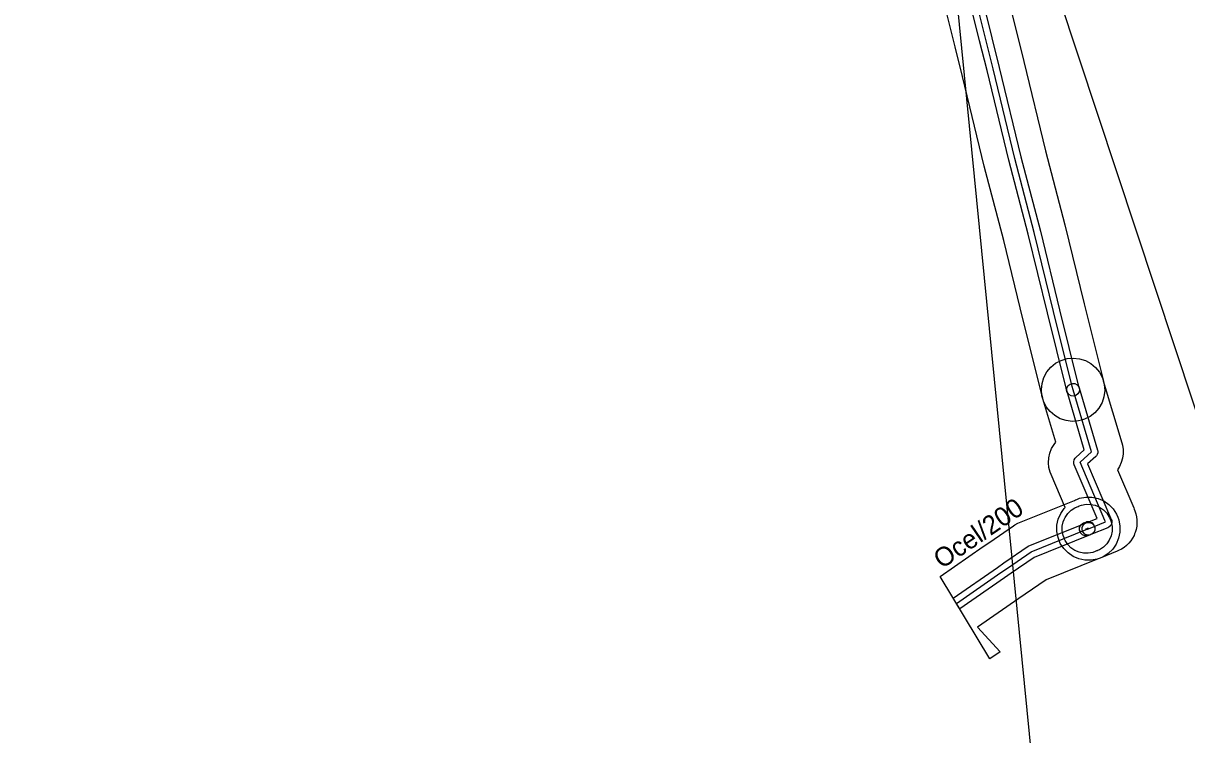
# Model space of a CAD drawing. Extents: x -555222 to -543220, y -1067119 to -1030889.
# Drawn here: x -550559 to -549821, y -1047415 to -1046964 of the extents above; entities that cross this region are included whole.
import ezdxf

# ---------------------------------------------------------------- set-up
doc = ezdxf.new("R2010")
doc.units = 0
for name, color, linetype in [('07_OCH_P A POPISY TI', 7, 'Continuous'), ('07_PLYNOVOD', 7, 'Continuous'), ('07_SDĚLOVACÍ', 7, 'Continuous')]:
    doc.layers.add(name, color=color, linetype=linetype)

msp = doc.modelspace()

# ---------------------------------------------------------------- linework, layer by layer
at = {"layer": '07_OCH_P A POPISY TI'}
for p, q in [((-549936.9, -1046937.01), (-549928.95, -1046969.41)), ((-549967.77, -1046979.03), (-549975.68, -1046946.81)), ((-549952.24, -1046975.18), (-549960.17, -1046942.89)), ((-549952.41, -1046940.93), (-549944.48, -1046973.26)), ((-549947.55, -1046993.93), (-549952.24, -1046975.18)), ((-549944.48, -1046973.26), (-549939.79, -1046992.01)), ((-549928.95, -1046969.41), (-549924.25, -1046988.19)), ((-549963.09, -1046997.75), (-549967.77, -1046979.03)), ((-549924.25, -1046988.19), (-549910.54, -1047044.87)), ((-549949.32, -1047054.65), (-549963.09, -1046997.75)), ((-549933.81, -1047050.74), (-549947.55, -1046993.93)), ((-549939.79, -1046992.01), (-549926.05, -1047048.78)), ((-549926.05, -1047048.78), (-549913.71, -1047095.83)), ((-549910.54, -1047044.87), (-549898.2, -1047091.9)), ((-549936.98, -1047101.72), (-549949.32, -1047054.65)), ((-549921.47, -1047097.79), (-549933.81, -1047050.74)), ((-549898.2, -1047091.9), (-549885.95, -1047141.98)), ((-549924.79, -1047151.56), (-549936.98, -1047101.72)), ((-549909.25, -1047147.73), (-549921.47, -1047097.79)), ((-549913.71, -1047095.83), (-549901.49, -1047145.81)), ((-549901.49, -1047145.81), (-549889.64, -1047193.48)), ((-549885.95, -1047141.98), (-549874.16, -1047189.41)), ((-549912.86, -1047199.57), (-549924.79, -1047151.56)), ((-549897.38, -1047195.5), (-549909.25, -1047147.73)), ((-549909.6, -1047185.21), (-549907.08, -1047182.18)), ((-549907.08, -1047182.18), (-549904.02, -1047179.7)), ((-549904.02, -1047179.7), (-549900.53, -1047177.86)), ((-549900.53, -1047177.86), (-549898.64, -1047177.3)), ((-549898.64, -1047177.3), (-549896.75, -1047176.74)), ((-549896.75, -1047176.74), (-549892.83, -1047176.38)), ((-549892.83, -1047176.38), (-549888.91, -1047176.8)), ((-549888.91, -1047176.8), (-549885.15, -1047177.96)), ((-549885.15, -1047177.96), (-549881.69, -1047179.84)), ((-549881.69, -1047179.84), (-549878.66, -1047182.36)), ((-549878.66, -1047182.36), (-549876.18, -1047185.42)), ((-549912.64, -1047192.43), (-549911.48, -1047188.67)), ((-549911.48, -1047188.67), (-549909.6, -1047185.21)), ((-549876.18, -1047185.42), (-549874.34, -1047188.91)), ((-549874.34, -1047188.91), (-549873.78, -1047190.8)), ((-549874.16, -1047189.41), (-549873.68, -1047191.15)), ((-549913.06, -1047196.35), (-549912.64, -1047192.43)), ((-549912.7, -1047200.27), (-549913.06, -1047196.35)), ((-549896.82, -1047197.55), (-549897.38, -1047195.5)), ((-549897.02, -1047196.85), (-549896.86, -1047195.27)), ((-549896.8, -1047197.62), (-549897.02, -1047196.85)), ((-549896.86, -1047195.27), (-549896.1, -1047193.87)), ((-549896.6, -1047198.31), (-549896.82, -1047197.55)), ((-549885.83, -1047234.62), (-549896.8, -1047197.62)), ((-549896.1, -1047193.87), (-549894.86, -1047192.87)), ((-549894.86, -1047192.87), (-549894.1, -1047192.64)), ((-549894.1, -1047192.64), (-549893.33, -1047192.42)), ((-549893.33, -1047192.42), (-549891.75, -1047192.58)), ((-549891.75, -1047192.58), (-549890.35, -1047193.34)), ((-549890.35, -1047193.34), (-549889.35, -1047194.58)), ((-549889.09, -1047197.76), (-549889.87, -1047199.14)), ((-549889.64, -1047193.48), (-549889.1, -1047195.41)), ((-549889.35, -1047194.58), (-549889.12, -1047195.34)), ((-549889.12, -1047195.34), (-549877.44, -1047234.75)), ((-549889.1, -1047195.41), (-549888.89, -1047196.18)), ((-549888.89, -1047196.18), (-549889.09, -1047197.76)), ((-549873.78, -1047190.8), (-549862.1, -1047230.21)), ((-549873.68, -1047191.15), (-549873.16, -1047193.05)), ((-549872.87, -1047196.98), (-549873.35, -1047200.89)), ((-549873.16, -1047193.05), (-549872.87, -1047196.98)), ((-549912.24, -1047201.81), (-549912.86, -1047199.57)), ((-549912.14, -1047202.16), (-549912.7, -1047200.27)), ((-549911.71, -1047203.71), (-549912.24, -1047201.81)), ((-549903.96, -1047229.76), (-549912.14, -1047202.16)), ((-549909.94, -1047207.23), (-549911.71, -1047203.71)), ((-549895.62, -1047199.57), (-549896.6, -1047198.31)), ((-549894.24, -1047200.35), (-549895.62, -1047199.57)), ((-549892.66, -1047200.55), (-549894.24, -1047200.35)), ((-549891.89, -1047200.34), (-549892.66, -1047200.55)), ((-549891.13, -1047200.12), (-549891.89, -1047200.34)), ((-549889.87, -1047199.14), (-549891.13, -1047200.12)), ((-549874.59, -1047204.63), (-549876.53, -1047208.06)), ((-549873.35, -1047200.89), (-549874.59, -1047204.63)), ((-549907.52, -1047210.33), (-549909.94, -1047207.23)), ((-549904.54, -1047212.91), (-549907.52, -1047210.33)), ((-549879.11, -1047211.04), (-549882.21, -1047213.46)), ((-549876.53, -1047208.06), (-549879.11, -1047211.04)), ((-549901.11, -1047214.85), (-549904.54, -1047212.91)), ((-549897.37, -1047216.09), (-549901.11, -1047214.85)), ((-549893.46, -1047216.57), (-549897.37, -1047216.09)), ((-549889.53, -1047216.28), (-549893.46, -1047216.57)), ((-549887.63, -1047215.76), (-549889.53, -1047216.28)), ((-549885.73, -1047215.23), (-549887.63, -1047215.76)), ((-549882.21, -1047213.46), (-549885.73, -1047215.23)), ((-549907.73, -1047236.69), (-549906.61, -1047233.81)), ((-549906.61, -1047233.81), (-549905.06, -1047231.14)), ((-549905.06, -1047231.14), (-549903.96, -1047229.76)), ((-549891.21, -1047239.52), (-549885.83, -1047234.62)), ((-549877.44, -1047234.75), (-549877.28, -1047235.29)), ((-549862.1, -1047230.21), (-549861.7, -1047231.55)), ((-549861.7, -1047231.55), (-549861.29, -1047234.33)), ((-549861.29, -1047234.33), (-549861.27, -1047237.13)), ((-549908.58, -1047242.79), (-549908.39, -1047239.71)), ((-549908.39, -1047239.71), (-549907.73, -1047236.69)), ((-549892.56, -1047242.23), (-549892.29, -1047241.02)), ((-549892.29, -1047241.02), (-549891.67, -1047239.94)), ((-549891.67, -1047239.94), (-549891.21, -1047239.52)), ((-549878.59, -1047238.85), (-549883.73, -1047243.53)), ((-549878.17, -1047238.47), (-549878.59, -1047238.85)), ((-549877.58, -1047237.51), (-549878.17, -1047238.47)), ((-549877.28, -1047236.42), (-549877.58, -1047237.51)), ((-549877.28, -1047235.29), (-549877.28, -1047236.42)), ((-549861.64, -1047239.91), (-549862.39, -1047242.62)), ((-549861.27, -1047237.13), (-549861.64, -1047239.91)), ((-549908.29, -1047245.87), (-549908.58, -1047242.79)), ((-549907.54, -1047248.86), (-549908.29, -1047245.87)), ((-549906.93, -1047250.29), (-549907.54, -1047248.86)), ((-549892.44, -1047243.47), (-549892.56, -1047242.23)), ((-549892.2, -1047244.04), (-549892.44, -1047243.47)), ((-549877.74, -1047278.16), (-549892.2, -1047244.04)), ((-549883.73, -1047243.53), (-549869.19, -1047277.83)), ((-549863.52, -1047245.19), (-549864.78, -1047247.24)), ((-549864.78, -1047247.24), (-549854.5, -1047271.48)), ((-549862.39, -1047242.62), (-549863.52, -1047245.19)), ((-549898.07, -1047271.2), (-549906.93, -1047250.29)), ((-549926.96, -1047280.78), (-549892.11, -1047266.68)), ((-549900.83, -1047274.97), (-549898.6, -1047271.72)), ((-549898.6, -1047271.72), (-549898.07, -1047271.2)), ((-549894.25, -1047272.95), (-549891.77, -1047271.34)), ((-549892.11, -1047266.68), (-549891.33, -1047266.36)), ((-549891.77, -1047271.34), (-549890.4, -1047270.78)), ((-549891.33, -1047266.36), (-549890.65, -1047266.09)), ((-549890.65, -1047266.09), (-549888.82, -1047265.36)), ((-549890.4, -1047270.78), (-549889.66, -1047270.49)), ((-549889.66, -1047270.49), (-549889, -1047270.22)), ((-549889, -1047270.22), (-549887.62, -1047269.67)), ((-549888.82, -1047265.36), (-549884.95, -1047264.64)), ((-549887.62, -1047269.67), (-549884.72, -1047269.13)), ((-549884.95, -1047264.64), (-549881.01, -1047264.68)), ((-549884.72, -1047269.13), (-549881.76, -1047269.17)), ((-549881.76, -1047269.17), (-549878.87, -1047269.78)), ((-549881.01, -1047264.68), (-549877.15, -1047265.5)), ((-549878.87, -1047269.78), (-549877.51, -1047270.36)), ((-549877.51, -1047270.36), (-549876.15, -1047270.95)), ((-549877.15, -1047265.5), (-549873.53, -1047267.05)), ((-549876.15, -1047270.95), (-549873.71, -1047272.62)), ((-549873.53, -1047267.05), (-549870.28, -1047269.28)), ((-549870.28, -1047269.28), (-549867.53, -1047272.1)), ((-549854.5, -1047271.48), (-549854.15, -1047272.28)), ((-549903.2, -1047282.45), (-549902.38, -1047278.6)), ((-549902.38, -1047278.6), (-549900.83, -1047274.97)), ((-549899.2, -1047280.19), (-549898.62, -1047278.83)), ((-549898.62, -1047278.83), (-549898.04, -1047277.47)), ((-549898.04, -1047277.47), (-549896.37, -1047275.02)), ((-549896.37, -1047275.02), (-549894.25, -1047272.95)), ((-549884.71, -1047280.95), (-549877.74, -1047278.16)), ((-549873.71, -1047272.62), (-549871.65, -1047274.74)), ((-549871.65, -1047274.74), (-549870.04, -1047277.22)), ((-549870.04, -1047277.22), (-549869.49, -1047278.59)), ((-549869.49, -1047278.59), (-549869.33, -1047279)), ((-549869.33, -1047279), (-549869.3, -1047279.08)), ((-549869.3, -1047279.08), (-549868.77, -1047280.37)), ((-549869.19, -1047277.83), (-549868.79, -1047278.74)), ((-549868.79, -1047278.74), (-549868.46, -1047279.48)), ((-549867.53, -1047272.1), (-549865.38, -1047275.4)), ((-549865.38, -1047275.4), (-549864.65, -1047277.23)), ((-549864.65, -1047277.23), (-549863.92, -1047279.06)), ((-549863.92, -1047279.06), (-549863.2, -1047282.93)), ((-549854.15, -1047272.28), (-549853.74, -1047273.2)), ((-549853.74, -1047273.2), (-549853.12, -1047275.11)), ((-549853.12, -1047275.11), (-549852.7, -1047277.07)), ((-549852.7, -1047277.07), (-549852.47, -1047279.07)), ((-549852.47, -1047279.07), (-549852.44, -1047281.08)), ((-549945.83, -1047293.1), (-549930.74, -1047282.8)), ((-549930.74, -1047282.8), (-549929.85, -1047282.2)), ((-549929.85, -1047282.2), (-549927.96, -1047281.18)), ((-549927.96, -1047281.18), (-549926.96, -1047280.78)), ((-549921.36, -1047295.77), (-549886.11, -1047281.51)), ((-549903.24, -1047286.39), (-549903.2, -1047282.45)), ((-549902.52, -1047290.26), (-549903.24, -1047286.39)), ((-549899.83, -1047286.05), (-549899.8, -1047283.09)), ((-549899.28, -1047288.96), (-549899.83, -1047286.05)), ((-549899.8, -1047283.09), (-549899.2, -1047280.19)), ((-549888.82, -1047285.47), (-549888.81, -1047283.87)), ((-549888.52, -1047286.21), (-549888.82, -1047285.47)), ((-549888.81, -1047283.87), (-549888.5, -1047283.14)), ((-549888.33, -1047286.68), (-549888.52, -1047286.21)), ((-549888.5, -1047283.14), (-549888.18, -1047282.41)), ((-549888.18, -1047282.41), (-549887.04, -1047281.29)), ((-549887.23, -1047285.41), (-549887.21, -1047283.82)), ((-549886.93, -1047286.15), (-549887.23, -1047285.41)), ((-549887.21, -1047283.82), (-549886.58, -1047282.35)), ((-549887.04, -1047281.29), (-549886.3, -1047280.99)), ((-549886.64, -1047286.88), (-549886.93, -1047286.15)), ((-549886.58, -1047282.35), (-549885.44, -1047281.24)), ((-549886.3, -1047280.99), (-549885.57, -1047280.7)), ((-549886.11, -1047281.51), (-549885.36, -1047281.21)), ((-549885.57, -1047280.7), (-549884.91, -1047280.44)), ((-549885.44, -1047281.24), (-549884.71, -1047280.95)), ((-549885.36, -1047281.21), (-549884.71, -1047280.95)), ((-549884.91, -1047280.44), (-549884.17, -1047280.14)), ((-549884.71, -1047280.95), (-549883.97, -1047280.65)), ((-549884.17, -1047280.14), (-549882.58, -1047280.16)), ((-549883.97, -1047280.65), (-549882.38, -1047280.67)), ((-549882.58, -1047280.16), (-549881.85, -1047280.47)), ((-549882.38, -1047280.67), (-549880.91, -1047281.3)), ((-549881.85, -1047280.47), (-549881.12, -1047280.79)), ((-549870.96, -1047284.06), (-549881.73, -1047288.37)), ((-549881.12, -1047280.79), (-549880, -1047281.93)), ((-549880.91, -1047281.3), (-549879.8, -1047282.44)), ((-549880, -1047281.93), (-549879.71, -1047282.67)), ((-549879.23, -1047285.5), (-549879.86, -1047286.97)), ((-549879.22, -1047285.48), (-549879.84, -1047286.94)), ((-549879.8, -1047282.44), (-549879.51, -1047283.17)), ((-549879.71, -1047282.67), (-549879.53, -1047283.12)), ((-549879.53, -1047283.12), (-549879.52, -1047283.15)), ((-549879.52, -1047283.15), (-549879.22, -1047283.89)), ((-549879.51, -1047283.17), (-549879.21, -1047283.91)), ((-549879.21, -1047283.91), (-549879.23, -1047285.5)), ((-549879.22, -1047283.89), (-549879.22, -1047285.48)), ((-549870.21, -1047283.76), (-549870.96, -1047284.06)), ((-549869.05, -1047282.61), (-549870.21, -1047283.76)), ((-549868.75, -1047281.86), (-549869.05, -1047282.61)), ((-549868.23, -1047286.22), (-549868.82, -1047289.12)), ((-549868.77, -1047280.37), (-549868.21, -1047283.27)), ((-549868.44, -1047281.11), (-549868.75, -1047281.86)), ((-549868.46, -1047279.48), (-549868.44, -1047281.11)), ((-549868.21, -1047283.27), (-549868.23, -1047286.22)), ((-549863.2, -1047282.93), (-549863.24, -1047286.87)), ((-549852.98, -1047285.05), (-549853.55, -1047286.98)), ((-549852.61, -1047283.08), (-549852.98, -1047285.05)), ((-549852.44, -1047281.08), (-549852.61, -1047283.08)), ((-549950.04, -1047295.98), (-549945.83, -1047293.1)), ((-549883.11, -1047288.93), (-549917.56, -1047302.87)), ((-549901.79, -1047292.09), (-549902.52, -1047290.26)), ((-549901.06, -1047293.92), (-549901.79, -1047292.09)), ((-549898.72, -1047290.33), (-549899.28, -1047288.96)), ((-549898.54, -1047290.79), (-549898.72, -1047290.33)), ((-549897.99, -1047292.16), (-549898.54, -1047290.79)), ((-549898.54, -1047290.79), (-549898.54, -1047290.79)), ((-549896.38, -1047294.64), (-549897.99, -1047292.16)), ((-549888.32, -1047286.7), (-549888.33, -1047286.68)), ((-549888.03, -1047287.44), (-549888.32, -1047286.7)), ((-549886.92, -1047288.58), (-549888.03, -1047287.44)), ((-549885.45, -1047289.21), (-549886.92, -1047288.58)), ((-549885.53, -1047288.02), (-549886.64, -1047286.88)), ((-549884.06, -1047288.65), (-549885.53, -1047288.02)), ((-549883.86, -1047289.23), (-549885.45, -1047289.21)), ((-549882.47, -1047288.67), (-549884.06, -1047288.65)), ((-549883.12, -1047288.93), (-549883.86, -1047289.23)), ((-549882.45, -1047288.66), (-549883.12, -1047288.93)), ((-549882.38, -1047288.63), (-549883.11, -1047288.93)), ((-549881.73, -1047288.37), (-549882.47, -1047288.67)), ((-549881.71, -1047288.36), (-549882.45, -1047288.66)), ((-549882.45, -1047288.66), (-549882.45, -1047288.66)), ((-549881.73, -1047288.37), (-549882.38, -1047288.63)), ((-549881, -1047288.08), (-549881.73, -1047288.37)), ((-549880.97, -1047288.06), (-549881.71, -1047288.36)), ((-549879.86, -1047286.97), (-549881, -1047288.08)), ((-549879.84, -1047286.94), (-549880.97, -1047288.06)), ((-549869.97, -1047291.84), (-549871.62, -1047294.29)), ((-549868.82, -1047289.12), (-549869.97, -1047291.84)), ((-549864.06, -1047290.73), (-549865.61, -1047294.35)), ((-549863.24, -1047286.87), (-549864.06, -1047290.73)), ((-549857.64, -1047293.83), (-549859.07, -1047295.25)), ((-549856.37, -1047292.28), (-549857.64, -1047293.83)), ((-549855.25, -1047290.61), (-549856.37, -1047292.28)), ((-549854.31, -1047288.84), (-549855.25, -1047290.61)), ((-549853.93, -1047287.91), (-549854.31, -1047288.84)), ((-549853.55, -1047286.98), (-549853.93, -1047287.91)), ((-549977.24, -1047314.89), (-549950.04, -1047295.98)), ((-549936.81, -1047306.32), (-549921.36, -1047295.77)), ((-549898.91, -1047297.22), (-549901.06, -1047293.92)), ((-549896.16, -1047300.04), (-549898.91, -1047297.22)), ((-549894.31, -1047296.75), (-549896.38, -1047294.64)), ((-549892.91, -1047302.27), (-549896.16, -1047300.04)), ((-549891.88, -1047298.42), (-549894.31, -1047296.75)), ((-549889.16, -1047299.59), (-549891.88, -1047298.42)), ((-549886.27, -1047300.2), (-549889.16, -1047299.59)), ((-549883.32, -1047300.24), (-549886.27, -1047300.2)), ((-549880.41, -1047299.7), (-549883.32, -1047300.24)), ((-549879.04, -1047299.15), (-549880.41, -1047299.7)), ((-549878.96, -1047299.11), (-549879.04, -1047299.15)), ((-549878.93, -1047299.11), (-549878.96, -1047299.11)), ((-549878.07, -1047298.76), (-549878.93, -1047299.11)), ((-549877.67, -1047298.6), (-549878.07, -1047298.76)), ((-549877.66, -1047298.59), (-549877.67, -1047298.6)), ((-549877.56, -1047298.55), (-549877.66, -1047298.59)), ((-549876.19, -1047297.99), (-549877.56, -1047298.55)), ((-549873.73, -1047296.37), (-549876.19, -1047297.99)), ((-549865.02, -1047298.92), (-549875.79, -1047303.23)), ((-549870.66, -1047300.35), (-549873.96, -1047302.5)), ((-549871.62, -1047294.29), (-549873.73, -1047296.37)), ((-549867.84, -1047297.6), (-549870.66, -1047300.35)), ((-549865.61, -1047294.35), (-549867.84, -1047297.6)), ((-549864.09, -1047298.54), (-549865.02, -1047298.92)), ((-549862.31, -1047297.62), (-549864.09, -1047298.54)), ((-549860.63, -1047296.51), (-549862.31, -1047297.62)), ((-549859.07, -1047295.25), (-549860.63, -1047296.51)), ((-549940.96, -1047309.16), (-549936.81, -1047306.32)), ((-549917.56, -1047302.87), (-549932.29, -1047312.92)), ((-549877.11, -1047303.76), (-549909.96, -1047317.05)), ((-549889.28, -1047303.82), (-549892.91, -1047302.27)), ((-549885.43, -1047304.64), (-549889.28, -1047303.82)), ((-549881.49, -1047304.68), (-549885.43, -1047304.64)), ((-549877.62, -1047303.96), (-549881.49, -1047304.68)), ((-549875.79, -1047303.23), (-549877.62, -1047303.96)), ((-549876.41, -1047303.48), (-549877.11, -1047303.76)), ((-549875.79, -1047303.23), (-549876.41, -1047303.48)), ((-549873.96, -1047302.5), (-549875.79, -1047303.23)), ((-549945.76, -1047367.18), (-549977.24, -1047314.89)), ((-549968.97, -1047328.63), (-549940.96, -1047309.16)), ((-549936.42, -1047315.74), (-549964.83, -1047335.5)), ((-549932.29, -1047312.92), (-549936.42, -1047315.74)), ((-549909.96, -1047317.05), (-549923.27, -1047326.14)), ((-549964.83, -1047335.5), (-549968.97, -1047328.63)), ((-549927.34, -1047328.92), (-549953.64, -1047347.2)), ((-549923.27, -1047326.14), (-549927.34, -1047328.92)), ((-549953.64, -1047347.2), (-549939.28, -1047362.73)), ((-549939.28, -1047362.73), (-549945.76, -1047367.18))]:
    msp.add_line(p, q, dxfattribs=at)
at = {"layer": '07_PLYNOVOD'}
for points in [[(-549892.96, -1047196.48), (-549893.51, -1047194.49), (-549905.37, -1047146.77), (-549917.59, -1047096.81), (-549929.93, -1047049.76), (-549943.67, -1046992.97), (-549948.36, -1046974.22), (-549956.29, -1046941.91)], [(-549883.22, -1047284.66), (-549872.45, -1047280.35), (-549872.86, -1047279.42), (-549888.52, -1047242.48), (-549881.28, -1047235.89), (-549892.96, -1047196.48)], [(-549966.9, -1047332.06), (-549938.69, -1047312.45), (-549934.55, -1047309.62), (-549919.46, -1047299.32), (-549884.61, -1047285.22), (-549883.87, -1047284.92), (-549883.22, -1047284.66)], [(-549884.61, -1047285.22), (-549884.62, -1047285.19), (-549884.82, -1047284.71), (-549884.09, -1047284.41), (-549883.42, -1047284.15), (-549883.23, -1047284.63), (-549883.22, -1047284.66)]]:
    msp.add_lwpolyline(points, dxfattribs=at)
at = {"layer": '07_SDĚLOVACÍ'}
for p, q in [((-555221.67, -1030889), (-543220.07, -1067118.92)), ((-550531.78, -1041228.78), (-549789.42, -1048745))]:
    msp.add_line(p, q, dxfattribs=at)

# ---------------------------------------------------------------- texts
at = {"layer": '07_OCH_P A POPISY TI'}
msp.add_text('Ocel/200', height=12, rotation=34.31632, dxfattribs=at).set_placement((-549976.27, -1047310.48))

doc.saveas('drawing.dxf')
